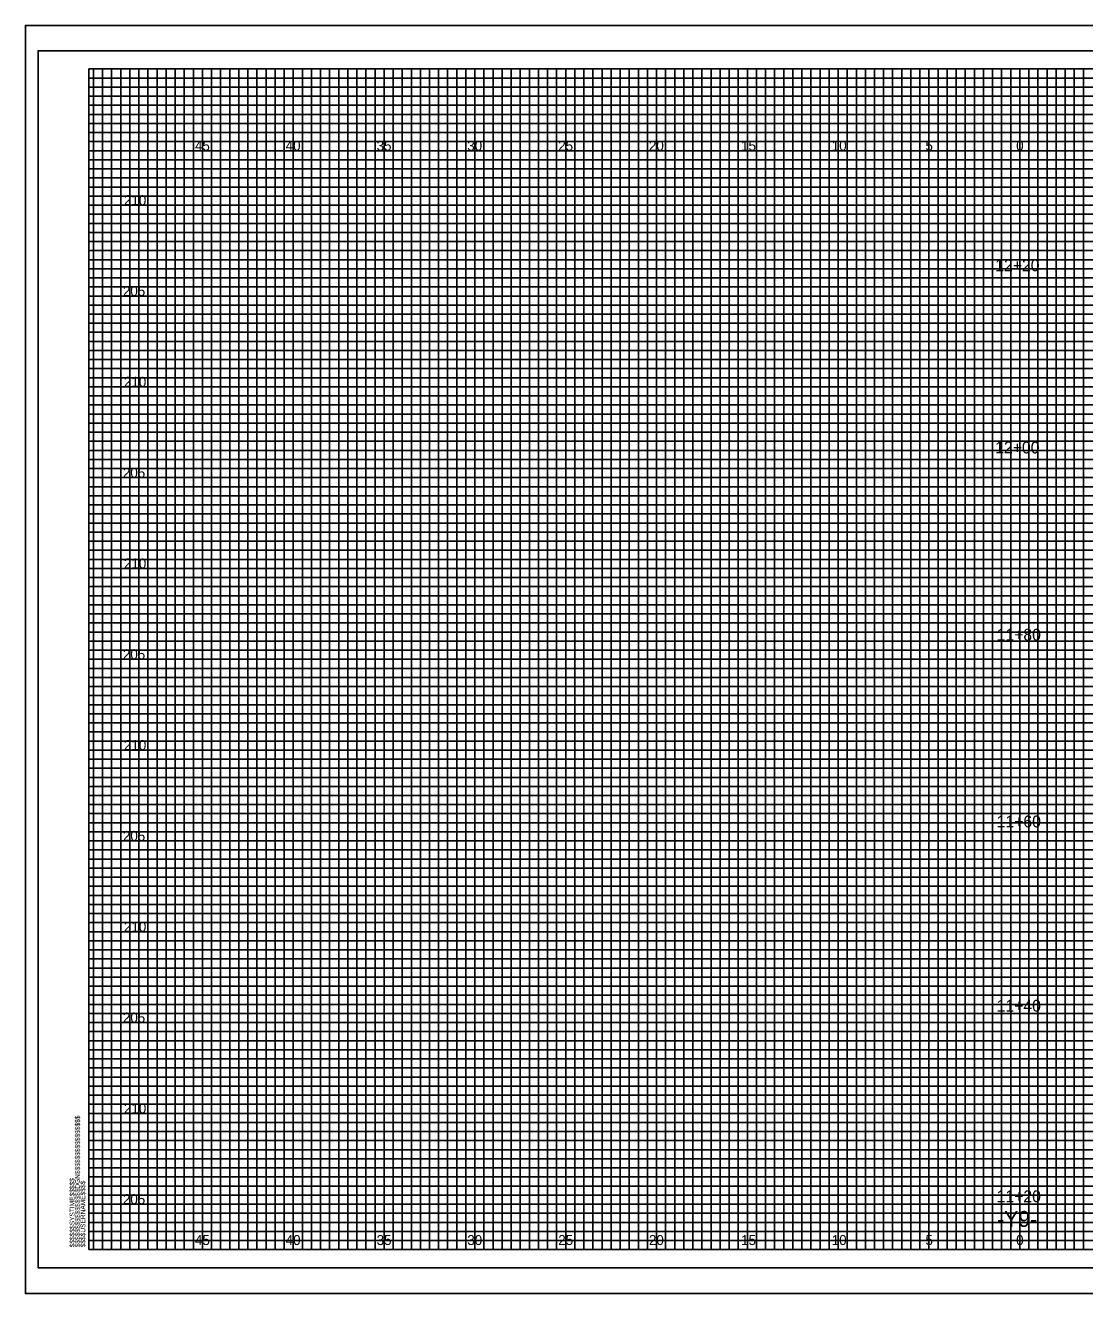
# Model space of a CAD drawing. Extents: x -4 to 103, y -2 to 492.
# Drawn here: x -3.5 to 54.8, y 68.4 to 138.2 of the extents above; entities that cross this region are included whole.
import ezdxf

# ---------------------------------------------------------------- set-up
doc = ezdxf.new("R2010")
doc.units = 0
for name, color, linetype in [('Old_Level_10', 7, 'Continuous'), ('Old_Level_16', 7, 'Continuous'), ('Old_Level_3', 7, 'Continuous'), ('Old_Level_5', 7, 'Continuous'), ('Old_Level_8', 7, 'Continuous'), ('Prop Dimension', 7, 'Continuous'), ('Prop Terminator CELL', 7, 'Continuous'), ('Prop XS Finish Grade', 7, 'Continuous'), ('Prop XS Finish Grade Earthwork', 7, 'Continuous'), ('Prop XS SE Text', 7, 'Continuous'), ('Prop XSC Text', 7, 'Continuous')]:
    doc.layers.add(name, color=color, linetype=linetype)

msp = doc.modelspace()

# ---------------------------------------------------------------- linework, layer by layer
at = {"layer": 'Old_Level_10'}
for p, q in [((1.25, 70.825), (1.25, 135.825)), ((3.75, 70.825), (3.75, 135.825)), ((6.25, 70.825), (6.25, 135.825)), ((8.75, 70.825), (8.75, 135.825)), ((11.25, 70.825), (11.25, 135.825)), ((13.75, 70.825), (13.75, 135.825)), ((16.25, 70.825), (16.25, 135.825)), ((18.75, 70.825), (18.75, 135.825)), ((21.25, 70.825), (21.25, 135.825)), ((23.75, 70.825), (23.75, 135.825)), ((26.25, 70.825), (26.25, 135.825)), ((28.75, 70.825), (28.75, 135.825)), ((31.25, 70.825), (31.25, 135.825)), ((33.75, 70.825), (33.75, 135.825)), ((36.25, 70.825), (36.25, 135.825)), ((38.75, 70.825), (38.75, 135.825)), ((41.25, 70.825), (41.25, 135.825)), ((43.75, 70.825), (43.75, 135.825)), ((46.25, 70.825), (46.25, 135.825)), ((48.75, 70.825), (48.75, 135.825)), ((51.25, 70.825), (51.25, 135.825)), ((53.75, 70.825), (53.75, 135.825)), ((0, 133.325), (74.25, 133.325)), ((0, 130.825), (102.5, 130.825)), ((0, 128.325), (102.5, 128.325)), ((0, 125.825), (102.5, 125.825)), ((0, 123.325), (102.5, 123.325)), ((0, 120.825), (102.5, 120.825)), ((0, 118.325), (102.5, 118.325)), ((0, 115.825), (102.5, 115.825)), ((0, 113.325), (102.5, 113.325)), ((0, 110.825), (102.5, 110.825)), ((0, 108.325), (102.5, 108.325)), ((0, 105.825), (102.5, 105.825)), ((0, 103.325), (102.5, 103.325)), ((0, 100.825), (102.5, 100.825)), ((0, 98.325), (102.5, 98.325)), ((0, 95.825), (102.5, 95.825)), ((0, 93.325), (102.5, 93.325)), ((0, 90.825), (102.5, 90.825)), ((0, 88.325), (102.5, 88.325)), ((0, 85.825), (102.5, 85.825)), ((0, 83.325), (102.5, 83.325)), ((0, 80.825), (102.5, 80.825)), ((0, 78.325), (102.5, 78.325)), ((0, 75.825), (102.5, 75.825)), ((0, 73.325), (102.5, 73.325))]:
    msp.add_line(p, q, dxfattribs=at)
at = {"layer": 'Old_Level_3'}
for p, q in [((-3.5, 138.225), (103.4, 138.225)), ((-3.5, 138.225), (-3.5, 68.4)), ((-3.5, 68.4), (103.4, 68.4))]:
    msp.add_line(p, q, dxfattribs=at)
at = {"layer": 'Old_Level_5'}
msp.add_lwpolyline([(103.4, 138.225), (-3.5, 138.225), (-3.5, 68.4), (103.4, 68.4)], close=True, dxfattribs=at)
at = {"layer": 'Old_Level_8'}
for points in [[(1.25, 70.825), (1.25, 135.825), (3.75, 135.825), (3.75, 70.825), (6.25, 70.825), (6.25, 135.825), (8.75, 135.825), (8.75, 70.825), (11.25, 70.825), (11.25, 135.825), (13.75, 135.825), (13.75, 70.825), (16.25, 70.825), (16.25, 135.825), (18.75, 135.825), (18.75, 70.825), (21.25, 70.825), (21.25, 135.825), (23.75, 135.825), (23.75, 70.825), (26.25, 70.825), (26.25, 135.825), (28.75, 135.825), (28.75, 70.825), (31.25, 70.825), (31.25, 135.825), (33.75, 135.825), (33.75, 70.825), (36.25, 70.825), (36.25, 135.825), (38.75, 135.825), (38.75, 70.825), (41.25, 70.825), (41.25, 135.825), (43.75, 135.825), (43.75, 70.825), (46.25, 70.825), (46.25, 135.825), (48.75, 135.825), (48.75, 70.825), (51.25, 70.825), (51.25, 135.825), (53.75, 135.825), (53.75, 70.825)], [(102.5, 130.825), (0, 130.825), (0, 133.325), (74.25, 133.325)], [(102.5, 125.825), (0, 125.825), (0, 128.325), (102.5, 128.325)], [(102.5, 120.825), (0, 120.825), (0, 123.325), (102.5, 123.325)], [(102.5, 115.825), (0, 115.825), (0, 118.325), (102.5, 118.325)], [(102.5, 110.825), (0, 110.825), (0, 113.325), (102.5, 113.325)], [(102.5, 105.825), (0, 105.825), (0, 108.325), (102.5, 108.325)], [(102.5, 100.825), (0, 100.825), (0, 103.325), (102.5, 103.325)], [(102.5, 95.825), (0, 95.825), (0, 98.325), (102.5, 98.325)], [(102.5, 90.825), (0, 90.825), (0, 93.325), (102.5, 93.325)], [(102.5, 85.825), (0, 85.825), (0, 88.325), (102.5, 88.325)], [(102.5, 80.825), (0, 80.825), (0, 83.325), (102.5, 83.325)], [(102.5, 75.825), (0, 75.825), (0, 78.325), (102.5, 78.325)], [(0, 73.325), (102.5, 73.325)]]:
    msp.add_lwpolyline(points, dxfattribs=at)
at = {"layer": 'Prop Dimension'}
for points in [[(0.25, 70.825), (0.25, 135.825), (0.75, 135.825), (0.75, 70.825), (1.75, 70.825), (1.75, 135.825), (2.25, 135.825), (2.25, 70.825), (2.75, 70.825), (2.75, 135.825), (3.25, 135.825), (3.25, 70.825), (4.25, 70.825), (4.25, 135.825), (4.75, 135.825), (4.75, 70.825), (5.25, 70.825), (5.25, 135.825), (5.75, 135.825), (5.75, 70.825), (6.75, 70.825), (6.75, 135.825), (7.25, 135.825), (7.25, 70.825), (7.75, 70.825), (7.75, 135.825), (8.25, 135.825), (8.25, 70.825), (9.25, 70.825), (9.25, 135.825), (9.75, 135.825), (9.75, 70.825), (10.25, 70.825), (10.25, 135.825), (10.75, 135.825), (10.75, 70.825), (11.75, 70.825), (11.75, 135.825), (12.25, 135.825), (12.25, 70.825), (12.75, 70.825), (12.75, 135.825), (13.25, 135.825), (13.25, 70.825), (14.25, 70.825), (14.25, 135.825), (14.75, 135.825), (14.75, 70.825), (15.75, 70.825), (15.25, 70.825), (15.25, 135.825), (15.75, 135.825), (15.75, 70.825), (16.75, 70.825), (16.75, 135.825), (17.25, 135.825), (17.25, 70.825), (17.75, 70.825), (17.75, 135.825), (18.25, 135.825), (18.25, 70.825), (19.25, 70.825), (19.25, 135.825), (19.75, 135.825), (19.75, 70.825), (20.25, 70.825), (20.25, 135.825), (20.75, 135.825), (20.75, 70.825), (21.75, 70.825), (21.75, 135.825), (22.25, 135.825), (22.25, 70.825), (22.75, 70.825), (22.75, 135.825), (23.25, 135.825), (23.25, 70.825), (24.25, 70.825), (24.25, 135.825), (24.75, 135.825), (24.75, 70.825), (25.25, 70.825), (25.25, 135.825), (25.75, 135.825), (25.75, 70.825), (26.75, 70.825), (26.75, 135.825), (27.25, 135.825), (27.25, 70.825), (27.75, 70.825), (27.75, 135.825), (28.25, 135.825), (28.25, 70.825), (29.25, 70.825), (29.25, 135.825), (29.75, 135.825), (29.75, 70.825), (30.25, 70.825), (30.25, 135.825), (30.75, 135.825), (30.75, 70.825)], [(30.75, 70.825), (31.75, 70.825), (31.75, 135.825), (32.25, 135.825), (32.25, 70.825), (32.75, 70.825), (32.75, 135.825), (33.25, 135.825), (33.25, 70.825), (34.25, 70.825), (34.25, 135.825), (34.75, 135.825), (34.75, 70.825), (35.25, 70.825), (35.25, 135.825), (35.75, 135.825), (35.75, 70.825), (36.75, 70.825), (36.75, 135.825), (37.25, 135.825), (37.25, 70.825), (37.75, 70.825), (37.75, 135.825), (37.75, 70.825)], [(38.25, 135.825), (38.25, 70.825), (39.25, 70.825), (39.25, 135.825), (39.75, 135.825), (39.75, 70.825), (40.25, 70.825), (40.25, 135.825), (40.75, 135.825), (40.75, 70.825), (41.75, 70.825), (41.75, 135.825), (42.25, 135.825), (42.25, 70.825), (42.75, 70.825), (42.75, 135.825), (43.25, 135.825), (43.25, 70.825), (43.75, 70.825), (44.25, 70.825), (44.25, 135.825), (44.75, 135.825), (44.75, 70.825), (45.25, 70.825), (45.25, 135.825), (45.75, 135.825), (45.75, 70.825), (46.75, 70.825), (46.75, 135.825), (47.25, 135.825), (47.25, 70.825), (47.75, 70.825), (47.75, 135.825), (48.25, 135.825), (48.25, 70.825), (49.25, 70.825), (49.25, 135.825), (49.75, 135.825), (49.75, 70.825), (50.25, 70.825), (50.25, 135.825), (50.75, 135.825), (50.75, 70.825), (51.75, 70.825), (51.75, 135.825), (52.25, 135.825), (52.25, 70.825), (52.75, 70.825), (52.75, 135.825), (53.25, 135.825), (53.25, 70.825), (54.25, 70.825), (54.25, 135.825), (54.75, 135.825), (54.75, 70.825), (55.25, 70.825)], [(0, 132.825), (0, 133.825), (74.25, 133.825), (74.25, 134.325), (0, 134.325), (0, 134.825), (74.25, 134.825), (74.25, 135.325), (0, 135.325)], [(102.5, 132.825), (0, 132.825)], [(102.5, 131.825), (0, 131.825), (0, 132.325), (102.5, 132.325)], [(102.5, 130.325), (0, 130.325), (0, 131.325), (102.5, 131.325)], [(102.5, 129.325), (0, 129.325), (0, 129.825), (102.5, 129.825)], [(102.5, 127.825), (0, 127.825), (0, 128.825), (102.5, 128.825)], [(102.5, 126.825), (0, 126.825), (0, 127.325), (102.5, 127.325)], [(102.5, 125.325), (0, 125.325), (0, 126.325), (102.5, 126.325)], [(102.5, 124.325), (0, 124.325), (0, 124.825), (102.5, 124.825)], [(0, 123.825), (102.5, 123.825)], [(102.5, 122.825), (0, 122.825)], [(102.5, 121.825), (0, 121.825), (0, 122.325), (102.5, 122.325)], [(102.5, 120.325), (0, 120.325), (0, 121.325), (102.5, 121.325)], [(102.5, 119.325), (0, 119.325), (0, 119.825), (102.5, 119.825)], [(102.5, 117.825), (0, 117.825), (0, 118.825), (102.5, 118.825)], [(102.5, 116.825), (0, 116.825), (0, 117.325), (102.5, 117.325)], [(102.5, 115.325), (0, 115.325), (0, 116.325), (102.5, 116.325)], [(102.5, 114.325), (0, 114.325), (0, 114.825), (102.5, 114.825)], [(102.5, 112.825), (0, 112.825), (0, 113.825), (102.5, 113.825)], [(102.5, 111.825), (0, 111.825), (0, 112.325), (102.5, 112.325)], [(102.5, 110.325), (0, 110.325), (0, 111.325), (102.5, 111.325)], [(102.5, 109.325), (0, 109.325), (0, 109.825), (102.5, 109.825)], [(102.5, 107.825), (0, 107.825), (0, 108.825), (102.5, 108.825)], [(102.5, 106.825), (0, 106.825), (0, 107.325), (102.5, 107.325)], [(102.5, 105.325), (0, 105.325), (0, 106.325), (102.5, 106.325)], [(102.5, 104.325), (0, 104.325), (0, 104.825), (102.5, 104.825)], [(102.5, 102.825), (0, 102.825), (0, 103.825), (102.5, 103.825)], [(102.5, 101.825), (0, 101.825), (0, 102.325)], [(0, 102.325), (102.5, 102.325)], [(102.5, 100.325), (0, 100.325), (0, 101.325), (102.5, 101.325)], [(102.5, 99.325), (0, 99.325), (0, 99.825), (102.5, 99.825)], [(102.5, 97.825), (0, 97.825), (0, 98.825), (102.5, 98.825)], [(102.5, 96.825), (0, 96.825), (0, 97.325), (102.5, 97.325)], [(102.5, 95.325), (0, 95.325), (0, 96.325), (102.5, 96.325)], [(102.5, 94.325), (0, 94.325), (0, 94.825), (102.5, 94.825)], [(102.5, 92.825), (0, 92.825), (0, 93.825), (102.5, 93.825)], [(102.5, 91.825), (0, 91.825), (0, 92.325), (102.5, 92.325)], [(102.5, 90.325), (0, 90.325), (0, 91.325), (102.5, 91.325)], [(102.5, 89.325), (0, 89.325), (0, 89.825), (102.5, 89.825)], [(102.5, 87.825), (0, 87.825), (0, 88.825), (102.5, 88.825)], [(102.5, 86.825), (0, 86.825), (0, 87.325), (102.5, 87.325)], [(102.5, 85.325), (0, 85.325), (0, 86.325), (102.5, 86.325)], [(102.5, 84.325), (0, 84.325), (0, 84.825), (102.5, 84.825)], [(102.5, 82.825), (0, 82.825), (0, 83.825), (102.5, 83.825)], [(102.5, 81.825), (0, 81.825), (0, 82.325), (102.5, 82.325)], [(102.5, 80.325), (0, 80.325), (0, 81.325), (102.5, 81.325)], [(102.5, 79.325), (0, 79.325), (0, 79.825), (102.5, 79.825)], [(102.5, 77.825), (0, 77.825), (0, 78.825), (102.5, 78.825)], [(102.5, 76.825), (0, 76.825), (0, 77.325), (102.5, 77.325)], [(102.5, 75.325), (0, 75.325), (0, 76.325), (102.5, 76.325)], [(102.5, 74.325), (0, 74.325), (0, 74.825), (102.5, 74.825)], [(102.5, 72.825), (0, 72.825), (0, 73.825), (102.5, 73.825)], [(102.5, 71.825), (0, 71.825), (0, 72.325), (102.5, 72.325)], [(0, 71.325), (102.5, 71.325)]]:
    msp.add_lwpolyline(points, dxfattribs=at)
at = {"layer": 'Prop XS SE Text'}
msp.add_lwpolyline([(103, 136.825), (-2.8, 136.825), (-2.8, 69.825), (103, 69.825)], close=True, dxfattribs=at)
at = {"layer": 'Prop XSC Text'}
msp.add_lwpolyline([(102.5, 135.825), (0, 135.825), (0, 70.825), (102.5, 70.825)], close=True, dxfattribs=at)

# ---------------------------------------------------------------- texts
at = {"layer": 'Old_Level_16'}
for s, p in [('45', (5.8399, 131.325)), ('40', (10.8313, 131.325)), ('35', (15.8399, 131.325)), ('30', (20.8313, 131.325)), ('25', (25.8399, 131.325)), ('20', (30.8313, 131.325)), ('15', (35.9058, 131.325)), ('10', (40.8971, 131.325)), ('5', (46.0574, 131.325)), ('0', (51.0488, 131.325)), ('0', (51.0488, 131.325)), ('45', (5.8399, 71.075)), ('40', (10.8313, 71.075)), ('35', (15.8399, 71.075)), ('30', (20.8313, 71.075)), ('25', (25.8399, 71.075)), ('20', (30.8313, 71.075)), ('15', (35.9058, 71.075)), ('10', (40.8971, 71.075)), ('5', (46.0574, 71.075)), ('0', (51.0488, 71.075)), ('0', (51.0488, 71.075))]:
    msp.add_text(s, height=0.55, dxfattribs=at).set_placement(p)
at = {"layer": 'Old_Level_8'}
msp.add_text('040397', height=0.0025, rotation=90, dxfattribs=at).set_placement((-0.0007, 135.8114))
at = {"layer": 'Prop Terminator CELL'}
msp.add_text('-Y9-', height=0.875, dxfattribs=at).set_placement((49.9985, 72.075))
at = {"layer": 'Prop XS Finish Grade'}
for s, p in [('12+20', (49.8934, 124.6865)), ('12+00', (49.8934, 114.6583)), ('11+80', (49.9712, 104.3536)), ('11+60', (49.9712, 94.0702)), ('11+40', (49.9712, 83.9272)), ('11+20', (49.9712, 73.4352))]:
    msp.add_text(s, height=0.65, dxfattribs=at).set_placement(p)
at = {"layer": 'Prop XS Finish Grade Earthwork'}
for s, p in [('210', (1.9296, 128.325)), ('205', (1.8724, 123.325)), ('210', (1.9296, 118.325)), ('205', (1.8724, 113.325)), ('210', (1.9296, 108.325)), ('205', (1.8724, 103.325)), ('210', (1.9296, 98.325)), ('205', (1.8724, 93.325)), ('210', (1.9296, 88.325)), ('205', (1.8724, 83.325)), ('210', (1.9296, 78.325)), ('205', (1.8724, 73.325))]:
    msp.add_text(s, height=0.55, dxfattribs=at).set_placement(p)
at = {"layer": 'Prop XSC Text'}
for s, p in [('$$$$$$$$$$$$$$$$DGN$$$$$$$$$$$$$$$$', (-0.5, 70.95)), ('$$$$$$SYSTIME$$$$$', (-0.7973, 70.9497)), ('$$$$USERNAME$$$$', (-0.2, 70.95))]:
    msp.add_text(s, height=0.2625, rotation=90, dxfattribs=at).set_placement(p)

doc.saveas('drawing.dxf')
